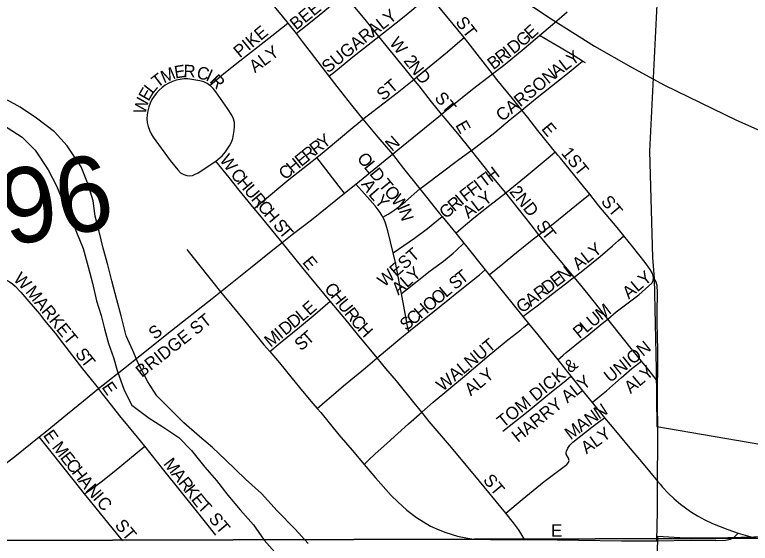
# Model space of a CAD drawing. Extents: x 1874609 to 2204689, y 815661 to 1281160.
# Drawn here: x 2019406 to 2022342, y 966454 to 968566 of the extents above; entities that cross this region are included whole.
import ezdxf

# ---------------------------------------------------------------- set-up
doc = ezdxf.new("R2010")
doc.units = 0
for name, color, linetype in [('GM_X_City_Street', 7, 'Continuous'), ('GM_X_City_Street_Text', 7, 'Continuous'), ('GM_X_Corporation', 7, 'Continuous'), ('GM_X_County_Road_Text', 7, 'Continuous'), ('GM_X_Major_River', 7, 'Continuous'), ('GM_X_Rail_Line', 7, 'Continuous'), ('GM_X_Section', 7, 'Continuous'), ('GM_X_State_Route', 7, 'Continuous'), ('GM_X_Township_Road', 7, 'Continuous'), ('GM_X_Township_Subdivision', 7, 'Continuous')]:
    doc.layers.add(name, color=color, linetype=linetype)

msp = doc.modelspace()

# ---------------------------------------------------------------- linework, layer by layer
at = {"layer": 'GM_X_City_Street'}
for points in [[(2020529.1, 968490.4), (2020548.7, 968506), (2020613.4, 968557.2), (2020689.7, 968620.7), (2020722.1, 968647.2)], [(2020859.5, 968479.3), (2020804.7, 968546.8), (2020722.1, 968647.2)], [(2020859.5, 968479.3), (2020896.6, 968508.1), (2020960.8, 968559), (2020998.7, 968590.5), (2021036.1, 968622.5), (2021061.4, 968644.3)], [(2021200, 968474.6), (2021061.4, 968644.3)], [(2021501.3, 968483.3), (2021552.1, 968527), (2021589.4, 968559.4), (2021611.2, 968576.9)], [(2020185.2, 968283.6), (2020203.6, 968299.1), (2020240.9, 968330.6), (2020304.7, 968381.1), (2020432.1, 968482.1), (2020470.7, 968511.8), (2020496.9, 968532.1)], [(2020660.4, 968320.2), (2020679.5, 968335.3), (2020755.2, 968398.1), (2020859.5, 968479.3)], [(2020998.8, 968307.8), (2020859.5, 968479.3)], [(2020998.8, 968307.8), (2021045.4, 968345.5), (2021133.1, 968418), (2021182.5, 968459.9), (2021200, 968474.6)], [(2021313.4, 968329.2), (2021214.7, 968456.7), (2021200, 968474.6)], [(2021313.4, 968329.2), (2021363.9, 968367.9), (2021440, 968430.5), (2021501.3, 968483.3)], [(2021672.7, 968380.5), (2021642.9, 968398.9), (2021587.6, 968432.2), (2021546.1, 968456.8), (2021501.3, 968483.3)], [(2021430.4, 968185), (2021485.1, 968229.6), (2021612.8, 968331), (2021650.5, 968362.1), (2021672.7, 968380.5)], [(2021684, 968373.6), (2021672.7, 968380.5)], [(2021110.2, 968168), (2021233.5, 968267.9), (2021313.4, 968329.2)], [(2021430.4, 968185), (2021392.7, 968231.5), (2021331.1, 968307.4), (2021313.4, 968329.2)], [(2020185.2, 968283.6), (2020174.9, 968290.9), (2020160.9, 968297.4), (2020145.7, 968301.8), (2020113.7, 968307.5), (2020097.8, 968309.4), (2020082.1, 968309.3), (2020066.4, 968307.4), (2020050.8, 968303.9), (2020035.7, 968298.9), (2020021.1, 968292.6), (2020007.3, 968284.7), (2019994.4, 968275.4), (2019982.6, 968264.8), (2019971.9, 968253), (2019962.3, 968240.2), (2019953.6, 968226.7), (2019946.5, 968212.6), (2019941, 968197.8), (2019937.3, 968182.3), (2019935, 968166.5), (2019934.2, 968150.6), (2019935.3, 968134.8), (2019938.4, 968119.5), (2019943.6, 968104.7), (2019950.6, 968090.5), (2019959.1, 968076.9), (2020026.4, 967984.2), (2020056.7, 967945.7), (2020067.9, 967934.8), (2020080.8, 967927), (2020093.6, 967923.2), (2020104.6, 967922), (2020115.6, 967923.2), (2020124.4, 967927.5), (2020138.4, 967934.7), (2020209.3, 967981.4)], [(2020796.1, 968148.7), (2020880.8, 968214.4), (2020932.4, 968253.9), (2020998.8, 968307.8)], [(2021110.2, 968168), (2021070.2, 968218.3), (2021019.9, 968281.9), (2020998.8, 968307.8)], [(2020209.3, 967981.4), (2020234.4, 968001.6), (2020247.8, 968018.7), (2020263.7, 968042.6), (2020271.1, 968057.3), (2020276.6, 968071.9), (2020279.5, 968087.8), (2020282.3, 968103.6), (2020283.9, 968119.5), (2020283.2, 968134.9), (2020279.4, 968149.8), (2020273.1, 968164.1), (2020255.8, 968191.3), (2020208.4, 968258.2), (2020198.5, 968270.8), (2020187.4, 968282), (2020185.2, 968283.6)], [(2021229.1, 968023.8), (2021259.2, 968046.5), (2021321.9, 968095.9), (2021384.2, 968147.3), (2021430.4, 968185)], [(2021563.5, 968017.9), (2021554.1, 968028.3), (2021544.2, 968040.2), (2021494.5, 968104), (2021454.4, 968155.3), (2021430.4, 968185)], [(2020612.5, 967996.1), (2020641.5, 968019), (2020764.1, 968122.5), (2020775.2, 968131.6), (2020796.1, 968148.7)], [(2020914.3, 968008.3), (2020977.8, 968060.7), (2021105.5, 968164.3), (2021110.2, 968168)], [(2021229.1, 968023.8), (2021174.4, 968091.4), (2021132.1, 968141.9), (2021110.2, 968168)], [(2021023.7, 967869.7), (2021043.6, 967884.7), (2021173.6, 967983.3), (2021223.1, 968019.4), (2021229.1, 968023.8)], [(2021365.8, 967854), (2021304.6, 967928), (2021229.1, 968023.8)], [(2020361.9, 967792.4), (2020387.6, 967813.7), (2020500.5, 967907.5), (2020612.5, 967996.1)], [(2020722.3, 967852.6), (2020701.5, 967879.2), (2020660.8, 967931.3), (2020621, 967984), (2020612.5, 967996.1)], [(2020768.1, 967889.4), (2020914.3, 968008.3)], [(2021365.8, 967854), (2021367.2, 967855.1), (2021455.9, 967927.5), (2021543.6, 968001.2), (2021563.5, 968017.9)], [(2021701.1, 967848.4), (2021676.2, 967879.3), (2021584.4, 967992.7), (2021574.3, 968005.5), (2021564.1, 968017.2), (2021563.5, 968017.9)], [(2020361.9, 967792.4), (2020302.6, 967864.8), (2020262.4, 967915.2), (2020209.3, 967981.4)], [(2020722.3, 967852.6), (2020768.1, 967889.4)], [(2020875.7, 967757.2), (2020873, 967762.4), (2020864.4, 967776), (2020845.2, 967802), (2020834.7, 967814.3), (2020813.5, 967838.7), (2020791.9, 967862.9), (2020768.1, 967889.4)], [(2020474.4, 967656.1), (2020513.4, 967687.4), (2020590.5, 967746.8), (2020722.3, 967852.6)], [(2020875.7, 967757.2), (2020896.6, 967769.8), (2020911.2, 967778.6), (2020939.1, 967798.1), (2020965.8, 967819.3), (2021023.7, 967869.7)], [(2021166.6, 967693.3), (2021188.7, 967712), (2021238.7, 967754.1), (2021302.8, 967804.8), (2021365.8, 967854)], [(2021498.8, 967687.2), (2021467.2, 967726.5), (2021365.8, 967854)], [(2021498.8, 967687.2), (2021561.7, 967736.2), (2021612.7, 967777), (2021663.5, 967818.1), (2021701.1, 967848.4)], [(2021838, 967682.2), (2021810.6, 967715.6), (2021737.8, 967802.8), (2021701.1, 967848.4)], [(2020474.4, 967656.1), (2020384.3, 967765), (2020361.9, 967792.4)], [(2020916.3, 967614.7), (2021002.2, 967673), (2021053.5, 967711.8), (2021090.7, 967742.6), (2021111.7, 967760)], [(2020916.3, 967614.7), (2020895.2, 967702.6), (2020886.6, 967733.8), (2020880.4, 967748.4), (2020875.7, 967757.2)], [(2021299.9, 967526.7), (2021321.3, 967544.2), (2021346.3, 967564.5), (2021371.3, 967585.2), (2021408.8, 967616.1), (2021472, 967666.3), (2021498.8, 967687.2)], [(2021639.2, 967517.6), (2021569.6, 967600.1), (2021518.2, 967663.1), (2021498.8, 967687.2)], [(2021639.2, 967517.6), (2021667.5, 967539.4), (2021742.6, 967600.5), (2021791.8, 967642.7), (2021816.3, 967663.6), (2021838, 967682.2)], [(2021956.4, 967515.5), (2021952.1, 967531.6), (2021942.3, 967548.4), (2021922.3, 967575.7), (2021872.4, 967640.3), (2021838, 967682.2)], [(2020227.6, 967458.7), (2020348, 967554.1), (2020437.1, 967626.1), (2020474.4, 967656.1)], [(2020665.8, 967421.1), (2020558, 967552.2), (2020496.7, 967628.3), (2020474.4, 967656.1)], [(2020950, 967452), (2020973.9, 967471.2), (2021012.5, 967502.1), (2021064.4, 967542.5), (2021117.3, 967581.6), (2021156.1, 967613.2), (2021168.5, 967624.6), (2021199.4, 967653.3)], [(2020093.3, 967628.4), (2020227.6, 967458.7)], [(2020950, 967452), (2020947.7, 967464.6), (2020925.6, 967576.2), (2020916.3, 967614.7)], [(2020978.9, 967299.8), (2021108.4, 967404.5), (2021197.2, 967476.1), (2021260.8, 967527.2), (2021284.3, 967546.2)], [(2019267.9, 967507.3), (2019306, 967511.4), (2019324.5, 967512.6), (2019339.4, 967512.2), (2019355.1, 967510), (2019370.7, 967506.5), (2019384.3, 967500.3), (2019396.9, 967491.4), (2019408.7, 967481), (2019430.6, 967457.5), (2019462.8, 967419.7), (2019504.8, 967370.3), (2019525.4, 967344.3), (2019567.4, 967294.2), (2019597.4, 967255.6), (2019677, 967151.7), (2019740.2, 967073)], [(2021434.6, 967360.7), (2021465.6, 967383.8), (2021491.4, 967402.9), (2021554.6, 967452.6), (2021605, 967491.4), (2021629.9, 967510.5), (2021639.2, 967517.6)], [(2021773.5, 967350.3), (2021765.6, 967360.2), (2021695, 967449.7), (2021653.7, 967500.4), (2021639.2, 967517.6)], [(2021773.5, 967350.3), (2021807.4, 967378.3), (2021897.4, 967446.7), (2021949.4, 967493.1), (2021954.9, 967503), (2021956.4, 967515.5)], [(2019740.2, 967073), (2019859.3, 967166.3), (2020013.2, 967289.6), (2020193.8, 967431.9), (2020227.6, 967458.7)], [(2020227.6, 967458.7), (2020240.4, 967443.1), (2020329.7, 967334.5), (2020400.4, 967247.5), (2020424.7, 967220.5)], [(2020978.9, 967299.8), (2020974.2, 967321), (2020970.7, 967336.8), (2020950, 967452)], [(2020424.7, 967220.5), (2020466.4, 967255.7), (2020543.5, 967317.3), (2020605.9, 967370.1), (2020665.8, 967421.1)], [(2020853.1, 967195), (2020774.7, 967290.2), (2020723.5, 967352.4), (2020665.8, 967421.1)], [(2021574, 967187.7), (2021594.9, 967205.8), (2021607.1, 967216.4), (2021669.9, 967266.8), (2021682.7, 967276.5), (2021757.7, 967337.2), (2021773.5, 967350.3)], [(2021908.6, 967181.8), (2021886.8, 967208), (2021866.1, 967232.8), (2021836, 967270.7), (2021773.5, 967350.3)], [(2021031.3, 966977.9), (2021077, 967017.5), (2021201.8, 967122.5), (2021300.6, 967205.9), (2021374.6, 967266.9), (2021426.3, 967306.9), (2021438.6, 967317.3), (2021457.1, 967333)], [(2020853.1, 967195), (2020943.5, 967271.3), (2020978.9, 967299.8)], [(2020424.7, 967220.5), (2020462.6, 967175.2), (2020513.9, 967113.2), (2020554.7, 967062.5), (2020596.6, 967012.8), (2020613.7, 966993.3)], [(2020613.7, 966993.3), (2020644.2, 967019.4), (2020668.7, 967040.8), (2020718.4, 967082.9), (2020806.4, 967155.6), (2020853.1, 967195)], [(2021031.3, 966977.9), (2021000.7, 967015.6), (2020930.2, 967103), (2020888.1, 967152.5), (2020853.1, 967195)], [(2021711.4, 967016.5), (2021742.1, 967042.1), (2021767.6, 967063.5), (2021804.1, 967094.9), (2021826.5, 967115.3), (2021869.7, 967152.7), (2021908.6, 967181.8)], [(2021972.3, 967102.3), (2021948.5, 967132.5), (2021928.3, 967158.2), (2021908.6, 967181.8)], [(2021354.9, 966901.6), (2021455.2, 966982.1), (2021542.6, 967053.8), (2021605.4, 967105), (2021626.5, 967122.1)], [(2019504.2, 966879.4), (2019528.1, 966898.6), (2019617, 966971), (2019680.3, 967022.8), (2019740.2, 967073)], [(2019925.6, 966842.1), (2019895.8, 966878.3), (2019825.7, 966963.5), (2019777.4, 967024.6), (2019757.1, 967051), (2019740.2, 967073)], [(2020613.7, 966993.3), (2020628, 966976.2), (2020700.4, 966887.9), (2020753.4, 966826.3), (2020801.2, 966769.3)], [(2020801.2, 966769.3), (2020820.3, 966787.4), (2020843.8, 966809.9), (2020892.3, 966854), (2020977.6, 966931.3), (2021031.3, 966977.9)], [(2021366.6, 966574.4), (2021242.1, 966725.2), (2021141.4, 966845.7), (2021061.1, 966941.2), (2021031.3, 966977.9)], [(2021366.6, 966574.4), (2021431.9, 966628.6), (2021519.2, 966701.1), (2021609.5, 966769.1), (2021616.2, 966776.4), (2021619, 966784.7), (2021616.6, 966794.5), (2021607.8, 966809.9), (2021607.1, 966816.9), (2021608.5, 966822.5), (2021613.4, 966833.7), (2021622.3, 966846.9), (2021634.2, 966857.9), (2021659.1, 966878.5), (2021710.3, 966918.3), (2021736.4, 966937.5), (2021760.8, 966955.4)], [(2019276.2, 966702.6), (2019283.2, 966707.6), (2019348.8, 966755.9), (2019413, 966806.3), (2019504.2, 966879.4)], [(2019685.4, 966651.7), (2019645.2, 966702.1), (2019546.4, 966826.4), (2019504.2, 966879.4)], [(2021971.6, 966703), (2021973.4, 966866.5)], [(2019685.4, 966651.7), (2019697.2, 966660.4), (2019751.3, 966699.8), (2019803.6, 966741.2), (2019925.6, 966842.1)], [(2020209, 966486.3), (2020126.5, 966590.8), (2020001.2, 966746.2), (2019925.6, 966842.1)], [(2020801.2, 966769.3), (2020846.3, 966715.6), (2020909.3, 966645.5), (2020935.1, 966619.8), (2020970.8, 966587.2), (2021009.8, 966557.8), (2021037.3, 966539.6), (2021066, 966523.1), (2021096, 966509.2), (2021126.9, 966497.5), (2021174.1, 966482.7), (2021206.4, 966475.4), (2021239.3, 966471.2), (2021305, 966469.3), (2021403.3, 966469.7), (2021441.4, 966469.7)], [(2021968.5, 966464.7), (2021971.2, 966582.5), (2021971.5, 966666.4), (2021971.6, 966703)], [(2019837.5, 966463.6), (2019812.2, 966494.8), (2019696.8, 966637.4), (2019685.4, 966651.7)], [(2021441.4, 966469.7), (2021425.8, 966495.2), (2021417, 966509.7), (2021397.2, 966535.9), (2021366.6, 966574.4)], [(2021441.4, 966469.7), (2021485, 966469.7), (2021828.4, 966464.2), (2021968.5, 966464.7)]]:
    msp.add_lwpolyline(points, dxfattribs=at)
at = {"layer": 'GM_X_Corporation'}
msp.add_lwpolyline([(2021994.3, 969114.6), (2021940.5, 968020.4), (2021952.4, 967595.4), (2021958.1, 967512.6), (2021966.7, 967149.9), (2021968.9, 966920.5), (2022426.6, 966842.7), (2022407.6, 966480.3), (2022252.1, 966475.7), (2022083.8, 966474.2), (2021972.4, 966481.7), (2021955.9, 965684.1), (2022311.7, 965684), (2022487.8, 965721.5), (2022739.9, 965940.6), (2022897, 965808.8), (2023273.1, 966173.5), (2023273.7, 966091.5), (2023269.2, 965891.4), (2023267.1, 965573.9), (2022902.8, 965434), (2022889.7, 965284.6), (2023053.5, 965276)], dxfattribs=at)
at = {"layer": 'GM_X_Major_River'}
for points in [[(2020578, 966454), (2020525.9, 966510.2), (2020453.8, 966584.4), (2020391.8, 966652.6), (2020327.7, 966710.8), (2020247.6, 966787), (2020195.6, 966837.2), (2020143.5, 966881.3), (2020081.5, 966935.4), (2019973.3, 967043.8), (2019937.3, 967099.9), (2019899.3, 967174.1), (2019877.3, 967224.3), (2019851.4, 967282.4), (2019831.4, 967362.7), (2019813.4, 967426.8), (2019793.5, 967503), (2019777.5, 967567.2), (2019759.6, 967633.4), (2019743.6, 967699.5), (2019727.6, 967761.7), (2019719.7, 967821.8), (2019699.7, 967888), (2019671.7, 967958.2), (2019615.7, 968042.4), (2019565.7, 968098.6), (2019493.6, 968152.8), (2019427.5, 968196.9), (2019377.4, 968225)], [(2019361.3, 968124.8), (2019435.4, 968076.6), (2019487.4, 968024.5), (2019539.4, 967946.2), (2019573.4, 967882.1), (2019601.4, 967813.9), (2019633.4, 967747.7), (2019653.4, 967697.6), (2019679.4, 967631.4), (2019699.3, 967559.2), (2019717.3, 967493), (2019733.3, 967422.8), (2019751.2, 967364.7), (2019765.2, 967310.5), (2019781.2, 967252.4), (2019801.2, 967196.2), (2019815.1, 967144.1), (2019843.1, 967065.9), (2019873.1, 967005.7), (2019943.2, 966953.6), (2019993.2, 966921.5), (2020061.3, 966877.3), (2020111.4, 966825.2), (2020165.4, 966759), (2020211.5, 966704.8), (2020257.5, 966646.6), (2020305.5, 966588.5), (2020359.6, 966528.3), (2020401.6, 966466.1), (2020475.7, 966383.9)]]:
    msp.add_lwpolyline(points, dxfattribs=at)
at = {"layer": 'GM_X_Rail_Line'}
msp.add_lwpolyline([(2021406.8, 968644.6), (2021547.8, 968550.1), (2021720.3, 968440.3), (2021864.9, 968357.5), (2022000.2, 968284.5), (2022287.1, 968144.6), (2022440.1, 968077.2), (2022596.2, 968017.2), (2022917.1, 967903.3), (2023004, 967875.9), (2023089.1, 967850.3), (2023211.1, 967816.4), (2023515.7, 967746.2), (2023663.7, 967721), (2023846.8, 967693.4), (2024121.9, 967663.2), (2024271.8, 967652.2)], dxfattribs=at)
at = {"layer": 'GM_X_Section'}
for points in [[(2019252.8, 971849.2), (2024559.1, 971862.4), (2024612.3, 966480.2), (2019314.1, 966465)], [(2024612.3, 966480.2), (2024657.5, 961100), (2019313.3, 961100.8), (2019314.1, 966465)]]:
    msp.add_lwpolyline(points, close=True, dxfattribs=at)
at = {"layer": 'GM_X_State_Route'}
for points in [[(2020430.2, 968613.5), (2020492.9, 968537.2), (2020496.9, 968532.1), (2020529.1, 968490.4), (2020553, 968459.4), (2020602.9, 968394.9), (2020660.4, 968320.2), (2020691.5, 968278.8), (2020720.9, 968242.2), (2020750.4, 968204.1), (2020796.1, 968148.7), (2020855.2, 968077.2), (2020914.3, 968008.3), (2020958.1, 967951.6), (2021023.7, 967869.7), (2021101.8, 967772.1), (2021111.7, 967760), (2021166.6, 967693.3), (2021199.4, 967653.3), (2021205.7, 967644.8), (2021284.3, 967546.2), (2021299.9, 967526.7), (2021318.2, 967503.6), (2021434.6, 967360.7), (2021457.1, 967333), (2021494.4, 967287.2), (2021574, 967187.7), (2021626.5, 967122.1), (2021669, 967068.9), (2021711.4, 967016.5), (2021760.8, 966955.4), (2021782.4, 966928.7), (2021824.1, 966879.9), (2021855.2, 966842.8), (2021907.3, 966779.9), (2021971.6, 966703), (2021981.8, 966690.8)], [(2021981.8, 966690.8), (2021991.8, 966678.9), (2022014.2, 966654.5), (2022038.3, 966631.7), (2022063.7, 966610.4), (2022103.8, 966581), (2022131.8, 966563.4), (2022160.9, 966547.5), (2022190.9, 966533.3), (2022252.8, 966509.1), (2022294.4, 966494.4)], [(2022294.4, 966494.4), (2022349.6, 966479.3), (2022388.1, 966471.4), (2022433.2, 966467.5), (2022475.1, 966468.7)]]:
    msp.add_lwpolyline(points, dxfattribs=at)
at = {"layer": 'GM_X_Township_Road'}
msp.add_lwpolyline([(2021973.4, 966866.5), (2021972.5, 966929)], dxfattribs=at)
at = {"layer": 'GM_X_Township_Subdivision'}
for points in [[(2021972.3, 967102.3), (2021972.6, 967129.8), (2021973.5, 967162.3), (2021973.2, 967227.9), (2021971.4, 967277.1), (2021971, 967338.3), (2021970.8, 967374.3), (2021972.1, 967456.4), (2021970.4, 967483.5), (2021965, 967502), (2021956.4, 967515.5)], [(2021971.8, 967059.2), (2021971.9, 967063.8), (2021972.3, 967102.3)], [(2021972.5, 966929), (2021971.5, 966997.8), (2021971.8, 967059.2)], [(2021968.5, 966464.7), (2022105.9, 966466.2), (2022205.1, 966465), (2022243, 966466.2), (2022262.6, 966470.5), (2022277.3, 966479.1), (2022294.4, 966494.4)]]:
    msp.add_lwpolyline(points, dxfattribs=at)

# ---------------------------------------------------------------- texts
at = {"layer": 'GM_X_City_Street_Text'}
for s, rotation, p in [('BEECH', 38.854, (2020529.5, 968502.2)), ('Y', 39.711, (2020902.4, 968525.6)), ('ST', 307.5735, (2021163, 968535.6)), ('PIKE', 39.8038, (2020305.1, 968391.4)), ('A', 36.9355, (2020837.5, 968475.8)), ('L', 38.1806, (2020873.6, 968503)), ('E', 42.27, (2021467.5, 968465)), ('SUGAR', 39.0375, (2020656.8, 968330.4)), ('G', 41.3846, (2021433.8, 968435.3)), ('W', 308.6758, (2020898.9, 968452.1)), ('D', 38.3861, (2021397.1, 968406.2)), ('ALY', 36.4679, (2020365.1, 968331.9)), ('I', 37.9018, (2021379.4, 968392.4)), ('2', 307.4068, (2020956.2, 968381.5)), ('B', 37.924, (2021317, 968343.7)), ('R', 37.9064, (2021348.2, 968368)), ('Y', 35.3268, (2021630.5, 968360.5)), ('N', 307.4228, (2020975, 968357.1)), ('L', 37.1704, (2021602.8, 968339.5)), ('M', 23.1173, (2020001.6, 968291.2)), ('E', 8.6942, (2020046.9, 968311)), ('R', 358.8586, (2020079.5, 968316.2)), ('C', 346.5411, (2020129.2, 968313.4)), ('I', 335.6248, (2020165.4, 968305)), ('D', 309.0229, (2021002.6, 968320.9)), ('CARSON', 39.1463, (2021352, 968136.8)), ('A', 37.2021, (2021567.8, 968312.9)), ('T', 36.9956, (2019976.2, 968271.6)), ('R', 314.313, (2020181.4, 968298.7)), ('L', 51.4469, (2019956.6, 968246.4)), ('ST', 40.2296, (2020876.7, 968220.2)), ('E', 60.1094, (2019940.2, 968217.5)), ('W', 75.5397, (2019927.3, 968165.4)), ('ST', 309.8092, (2021079.2, 968232.3)), ('E', 299.755, (2021163.7, 968125.3)), ('E', 309.8092, (2021506, 968109.1)), ('Y', 37.4207, (2020638.7, 968027.9)), ('N', 41.1879, (2020911.8, 968017.7)), ('R', 37.8026, (2020607.5, 968003.7)), ('R', 39.0997, (2020577, 967978.9)), ('1ST', 308.9264, (2021585.3, 968012.2)), ('W', 306.3252, (2020221.6, 967985.4)), ('H', 39.3922, (2020515.8, 967928.7)), ('E', 39.3893, (2020549.8, 967956.6)), ('O', 309.2402, (2020769.7, 967990.8)), ('C', 39.3765, (2020485.2, 967903.5)), ('L', 309.2429, (2020797.5, 967956.7)), ('C', 308.8729, (2020264.9, 967926.9)), ('D', 309.2402, (2020819.8, 967929.5)), ('T', 37.1322, (2021279.7, 967873)), ('H', 37.1711, (2021307.8, 967894.3)), ('H', 310.0457, (2020290.4, 967895.2)), ('T', 309.2529, (2020856, 967885.2)), ('I', 37.167, (2021262.1, 967859.7)), ('U', 310.1093, (2020318.8, 967861.5)), ('A', 304.0053, (2020787.3, 967888.4)), ('L', 310.9482, (2020815.9, 967846.7)), ('O', 309.2402, (2020878.2, 967857.9)), ('F', 38.5147, (2021206.7, 967816.7)), ('F', 37.1322, (2021234, 967838.4)), ('2ND', 308.9946, (2021378.5, 967858.2)), ('R', 310.0823, (2020347.1, 967827.8)), ('Y', 311.767, (2020839.5, 967819.6)), ('W', 308.2318, (2020905.9, 967824)), ('I', 40.7293, (2021190.5, 967802.7)), ('ALY', 37.2346, (2021216.9, 967749.7)), ('C', 310.0911, (2020372.7, 967797.5)), ('R', 40.7382, (2021160.5, 967776.8)), ('ST', 309.8092, (2021743.6, 967818.7)), ('H', 310.1102, (2020398.1, 967767.2)), ('N', 286.4648, (2020939, 967783.5)), ('G', 40.7459, (2021127.1, 967748.1)), ('S', 310.1064, (2020435, 967723.5)), ('S', 307.1322, (2021484.3, 967721.5)), ('T', 310.1064, (2020457.7, 967696.5)), ('T', 308.6111, (2021506.4, 967692.3)), ('ALY', 38.0509, (2021655.8, 967542.9)), ('WEST', 40.7617, (2020880.8, 967475.4)), ('E', 309.687, (2020551.9, 967575.8)), ('ALY', 40.8174, (2020937.4, 967443.5)), ('N', 37.7144, (2021596.2, 967497)), ('W', 315.0243, (2019397.8, 967506.9)), ('S', 39.5642, (2021164.5, 967464.7)), ('T', 38.2416, (2021191.4, 967487)), ('E', 37.307, (2021567.9, 967475.4)), ('ALY', 39.9689, (2021857.2, 967427.7)), ('D', 37.3311, (2021532.9, 967448.7)), ('MARKET', 309.286, (2019446.7, 967458)), ('C', 308.7888, (2020639.3, 967470.9)), ('H', 308.8013, (2020664.1, 967440.1)), ('O', 40.0139, (2021093.8, 967405.4)), ('L', 40.017, (2021127.5, 967433.7)), ('R', 37.3168, (2021501.4, 967424.7)), ('O', 40.0182, (2021060.1, 967377.1)), ('A', 37.3311, (2021466.4, 967398)), ('E', 41.3177, (2020582.2, 967361.7)), ('U', 308.8066, (2020691.7, 967405.8)), ('H', 40.0139, (2021026.4, 967348.8)), ('G', 37.3114, (2021431.4, 967371.3)), ('M', 37.4054, (2021747.4, 967342.7)), ('L', 39.4278, (2020553.7, 967338.2)), ('R', 308.7888, (2020719.3, 967371.5)), ('C', 40.0139, (2020996, 967323.3)), ('U', 39.7692, (2021714, 967314.9)), ('BRIDGE ST', 38.1565, (2019913.7, 967114.4)), ('D', 39.4586, (2020519.7, 967310.2)), ('C', 308.8063, (2020744.1, 967340.6)), ('S', 40.0294, (2020969.1, 967300.7)), ('S', 39.8092, (2019965.9, 967265.5)), ('D', 39.4469, (2020485.8, 967282.2)), ('H', 312.1171, (2020771, 967307.3)), ('P', 39.7566, (2021659.9, 967269.9)), ('L', 39.7758, (2021687, 967292.4)), ('M', 39.4534, (2020428, 967234.7)), ('I', 39.4248, (2020468.8, 967268.3)), ('T', 41.0383, (2020577, 967243.9)), ('S', 38.7281, (2020547.8, 967220.5)), ('WALNUT', 39.6838, (2021114.2, 967058.6)), ('UNION', 38.8533, (2021782.9, 967093.8)), ('S', 307.1322, (2019645.1, 967211.1)), ('T', 308.6318, (2019667.2, 967181.9)), ('TOM DICK &', 39.193, (2021356.4, 966913.5)), ('ALY', 39.2894, (2021226.5, 967040.9)), ('ALY', 40.0354, (2021864.6, 967049.8)), ('HARRY ALY', 38.5489, (2021414.5, 966855.1)), ('E', 305.1504, (2019751.7, 967077.5)), ('N', 32.9322, (2021737.7, 966948.4)), ('N', 35.7333, (2021702.5, 966923.1)), ('A', 36.8131, (2021667.5, 966896.9)), ('E', 305.5436, (2019517.6, 966885.3)), ('M', 36.8335, (2021625.2, 966865.2)), ('ALY', 35.5384, (2021688.5, 966808.7)), ('M', 307.9884, (2019552.6, 966837.2)), ('E', 308.0001, (2019585.1, 966795.6)), ('M', 307.9629, (2019997, 966771.2)), ('C', 308.0113, (2019606.7, 966767.9)), ('H', 307.9804, (2019631.1, 966736.7)), ('A', 307.971, (2020029.5, 966729.6)), ('A', 308.131, (2019658.3, 966701.9)), ('R', 307.9772, (2020056.6, 966694.9)), ('ST', 309.7984, (2021272.8, 966705.5)), ('N', 310.1578, (2019686.7, 966665.8)), ('K', 307.9804, (2020080.9, 966663.6)), ('I', 311.112, (2019715.7, 966631.5)), ('E', 307.9685, (2020108, 966629)), ('C', 311.2038, (2019730.2, 966614.8)), ('T', 313.2338, (2020132.9, 966597.4)), ('ST', 309.7984, (2020177.2, 966551.5)), ('ST', 309.7984, (2019803.2, 966525.1)), ('E', 0, (2021547.1, 966480.1))]:
    msp.add_text(s, height=50, rotation=rotation, dxfattribs=at).set_placement(p)
at = {"layer": 'GM_X_County_Road_Text'}
msp.add_text('C-2796', height=300, rotation=10.2412, dxfattribs=at).set_placement((2018521.3, 967486.1))

doc.saveas('drawing.dxf')
